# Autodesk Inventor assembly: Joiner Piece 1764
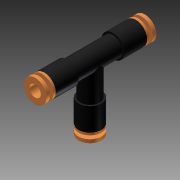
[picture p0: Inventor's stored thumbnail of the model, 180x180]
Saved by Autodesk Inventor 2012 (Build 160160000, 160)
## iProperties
Created: 2010-02
Part Number: Joiner Piece 1764
Document SubType Name: Assembly
Designer: jgehrig
Author: jgehrig
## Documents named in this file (3)
- R:\CAD Archives\Pneumatics_1764\Joiner_Piece_1764\Joiner_Piece_1764.iam
- R:\CAD Archives\Pneumatics_1764\Joiner_Piece_1764\Joiner_Base_1764.ipt
- R:\CAD Archives\Pneumatics_1764\Joiner_Piece_1764\Pneumatic_Screw_Part_2_1764.ipt
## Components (4 placed, 2 different names)
1. Joiner_Base_1764:1 — Insert:1, Insert:2, Insert:3
2. Pneumatic_Screw_Part_2_1764:1 — Insert:3
3. Pneumatic_Screw_Part_2_1764:2 — Insert:2
4. Pneumatic_Screw_Part_2_1764:3 — Insert:1
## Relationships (3: Insert 3)
- Insert:1: Joiner_Base_1764:1 ↔ Pneumatic_Screw_Part_2_1764:3
- Insert:2: Joiner_Base_1764:1 ↔ Pneumatic_Screw_Part_2_1764:2
- Insert:3: Joiner_Base_1764:1 ↔ Pneumatic_Screw_Part_2_1764:1
